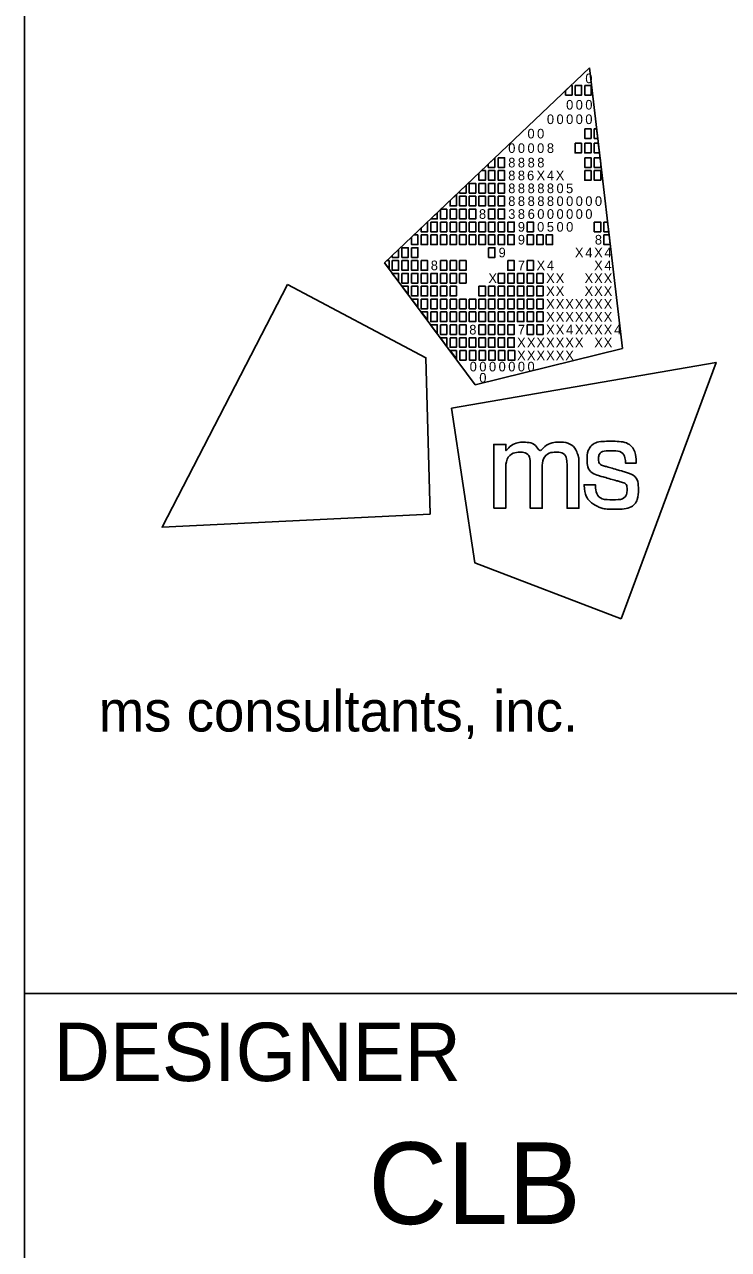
# Model space of a CAD drawing. Extents: x -0.2 to 34, y 0 to 22.
# Drawn here: x 32 to 33.207, y 2.061 to 4.16 of the extents above; entities that cross this region are included whole.
import ezdxf

# ---------------------------------------------------------------- set-up
doc = ezdxf.new("R2010")
doc.units = 0
doc.layers.add('SH_Border', color=7, linetype='Continuous')
doc.layers.add('SH_Data', color=7, linetype='Continuous')

msp = doc.modelspace()

# ---------------------------------------------------------------- linework, layer by layer
at = {"layer": 'SH_Border'}
for p, q in [((32, 0.5), (32, 21.5)), ((32.6175, 3.7519), (32.9688, 4.0861)), ((32.9688, 4.0861), (32.9688, 4.0861)), ((32.9688, 4.0861), (33.0253, 3.6052)), ((32.773, 3.543), (32.6175, 3.7519)), ((33.0253, 3.6052), (32.773, 3.543)), ((32, 2.5), (33.5, 2.5))]:
    msp.add_line(p, q, dxfattribs=at)
for points in [[(32.9279, 4.0472), (32.9369, 4.0558), (32.9389, 4.0558), (32.9389, 4.0393), (32.9279, 4.0393)], [(32.9444, 4.0558), (32.9554, 4.0558), (32.9554, 4.0393), (32.9444, 4.0393)], [(32.9609, 4.0558), (32.9719, 4.0558), (32.9719, 4.0393), (32.9609, 4.0393)], [(32.9606, 3.9815), (32.9716, 3.9815), (32.9716, 3.965), (32.9606, 3.965)], [(32.9771, 3.9815), (32.9811, 3.9815), (32.983, 3.965), (32.9771, 3.965)], [(32.9441, 3.9567), (32.9551, 3.9567), (32.9551, 3.9402), (32.9441, 3.9402)], [(32.9606, 3.9567), (32.9716, 3.9567), (32.9716, 3.9402), (32.9606, 3.9402)], [(32.9771, 3.9567), (32.984, 3.9567), (32.9859, 3.9402), (32.9771, 3.9402)], [(32.7953, 3.9211), (32.8064, 3.9316), (32.8064, 3.9154), (32.7953, 3.9154)], [(32.8123, 3.9319), (32.8233, 3.9319), (32.8233, 3.9154), (32.8123, 3.9154)], [(32.9606, 3.9319), (32.9716, 3.9319), (32.9716, 3.9154), (32.9606, 3.9154)], [(32.9771, 3.9319), (32.9869, 3.9319), (32.9881, 3.9218), (32.9881, 3.9154), (32.9771, 3.9154)], [(32.7958, 3.9099), (32.8068, 3.9099), (32.8068, 3.8934), (32.7958, 3.8934)], [(32.8123, 3.9099), (32.8233, 3.9099), (32.8233, 3.8934), (32.8123, 3.8934)], [(32.9606, 3.9099), (32.9716, 3.9099), (32.9716, 3.8934), (32.9606, 3.8934)], [(32.9771, 3.9099), (32.9881, 3.9099), (32.9881, 3.8934), (32.9771, 3.8934)], [(32.7627, 3.8879), (32.7737, 3.8879), (32.7737, 3.8714), (32.7627, 3.8714)], [(32.7793, 3.8879), (32.7903, 3.8879), (32.7903, 3.8714), (32.7793, 3.8714)], [(32.7958, 3.8879), (32.8068, 3.8879), (32.8068, 3.8714), (32.7958, 3.8714)], [(32.8123, 3.8879), (32.8233, 3.8879), (32.8233, 3.8714), (32.8123, 3.8714)], [(32.7462, 3.8659), (32.7572, 3.8659), (32.7572, 3.8494), (32.7462, 3.8494)], [(32.7627, 3.8659), (32.7737, 3.8659), (32.7737, 3.8494), (32.7627, 3.8494)], [(32.7793, 3.8659), (32.7903, 3.8659), (32.7903, 3.8494), (32.7793, 3.8494)], [(32.7958, 3.8659), (32.8068, 3.8659), (32.8068, 3.8494), (32.7958, 3.8494)], [(32.8123, 3.8659), (32.8233, 3.8659), (32.8233, 3.8494), (32.8123, 3.8494)], [(32.7297, 3.8439), (32.7407, 3.8439), (32.7407, 3.8273), (32.7297, 3.8273)], [(32.7462, 3.8439), (32.7572, 3.8439), (32.7572, 3.8273), (32.7462, 3.8273)], [(32.7627, 3.8439), (32.7737, 3.8439), (32.7737, 3.8273), (32.7627, 3.8273)], [(32.7958, 3.8439), (32.8068, 3.8439), (32.8068, 3.8273), (32.7958, 3.8273)], [(32.8123, 3.8439), (32.8233, 3.8439), (32.8233, 3.8273), (32.8123, 3.8273)], [(32.6967, 3.8218), (32.7077, 3.8218), (32.7077, 3.8053), (32.6967, 3.8053)], [(32.7132, 3.8218), (32.7242, 3.8218), (32.7242, 3.8053), (32.7132, 3.8053)], [(32.7297, 3.8218), (32.7407, 3.8218), (32.7407, 3.8053), (32.7297, 3.8053)], [(32.7462, 3.8218), (32.7572, 3.8218), (32.7572, 3.8053), (32.7462, 3.8053)], [(32.7627, 3.8218), (32.7737, 3.8218), (32.7737, 3.8053), (32.7627, 3.8053)], [(32.7793, 3.8218), (32.7903, 3.8218), (32.7903, 3.8053), (32.7793, 3.8053)], [(32.7958, 3.8218), (32.8068, 3.8218), (32.8068, 3.8053), (32.7958, 3.8053)], [(32.8123, 3.8218), (32.8233, 3.8218), (32.8233, 3.8053), (32.8123, 3.8053)], [(32.8288, 3.8218), (32.8398, 3.8218), (32.8398, 3.8053), (32.8288, 3.8053)], [(32.8618, 3.8218), (32.8728, 3.8218), (32.8728, 3.8053), (32.8618, 3.8053)], [(32.9771, 3.8218), (32.9881, 3.8218), (32.9881, 3.8053), (32.9771, 3.8053)], [(32.9935, 3.8218), (32.9998, 3.8218), (33.0018, 3.8053), (32.9935, 3.8053)], [(32.6802, 3.7998), (32.6912, 3.7998), (32.6912, 3.7833), (32.6802, 3.7833)], [(32.6967, 3.7998), (32.7077, 3.7998), (32.7077, 3.7833), (32.6967, 3.7833)], [(32.7132, 3.7998), (32.7242, 3.7998), (32.7242, 3.7833), (32.7132, 3.7833)], [(32.7297, 3.7998), (32.7407, 3.7998), (32.7407, 3.7833), (32.7297, 3.7833)], [(32.7462, 3.7998), (32.7572, 3.7998), (32.7572, 3.7833), (32.7462, 3.7833)], [(32.7627, 3.7998), (32.7737, 3.7998), (32.7737, 3.7833), (32.7627, 3.7833)], [(32.7793, 3.7998), (32.7903, 3.7998), (32.7903, 3.7833), (32.7793, 3.7833)], [(32.7958, 3.7998), (32.8068, 3.7998), (32.8068, 3.7833), (32.7958, 3.7833)], [(32.8123, 3.7998), (32.8233, 3.7998), (32.8233, 3.7833), (32.8123, 3.7833)], [(32.8288, 3.7998), (32.8398, 3.7998), (32.8398, 3.7833), (32.8288, 3.7833)], [(32.8618, 3.7998), (32.8728, 3.7998), (32.8728, 3.7833), (32.8618, 3.7833)], [(32.8783, 3.7998), (32.8893, 3.7998), (32.8893, 3.7833), (32.8783, 3.7833)], [(32.8947, 3.7998), (32.9057, 3.7998), (32.9057, 3.7833), (32.8947, 3.7833)], [(32.9935, 3.7998), (33.0024, 3.7998), (33.0044, 3.7833), (32.9935, 3.7833)], [(32.6471, 3.7778), (32.6581, 3.7778), (32.6581, 3.7613), (32.6471, 3.7613)], [(32.6637, 3.7778), (32.6747, 3.7778), (32.6747, 3.7613), (32.6637, 3.7613)], [(32.7958, 3.7778), (32.8068, 3.7778), (32.8068, 3.7613), (32.7958, 3.7613)], [(32.6306, 3.7558), (32.6416, 3.7558), (32.6416, 3.7393), (32.6306, 3.7393)], [(32.6471, 3.7558), (32.6581, 3.7558), (32.6581, 3.7393), (32.6471, 3.7393)], [(32.6637, 3.7558), (32.6747, 3.7558), (32.6747, 3.7393), (32.6637, 3.7393)], [(32.6802, 3.7558), (32.6912, 3.7558), (32.6912, 3.7393), (32.6802, 3.7393)], [(32.7132, 3.7558), (32.7242, 3.7558), (32.7242, 3.7393), (32.7132, 3.7393)], [(32.7297, 3.7558), (32.7407, 3.7558), (32.7407, 3.7393), (32.7297, 3.7393)], [(32.7462, 3.7558), (32.7572, 3.7558), (32.7572, 3.7393), (32.7462, 3.7393)], [(32.8288, 3.7558), (32.8398, 3.7558), (32.8398, 3.7393), (32.8288, 3.7393)], [(32.8618, 3.7558), (32.8728, 3.7558), (32.8728, 3.7393), (32.8618, 3.7393)], [(32.6306, 3.7338), (32.6416, 3.7338), (32.6416, 3.72)], [(32.6471, 3.7338), (32.6581, 3.7338), (32.6581, 3.7173), (32.6471, 3.7173)], [(32.6637, 3.7338), (32.6747, 3.7338), (32.6747, 3.7173), (32.6637, 3.7173)], [(32.6802, 3.7338), (32.6912, 3.7338), (32.6912, 3.7173), (32.6802, 3.7173)], [(32.6967, 3.7338), (32.7077, 3.7338), (32.7077, 3.7173), (32.6967, 3.7173)], [(32.7132, 3.7338), (32.7242, 3.7338), (32.7242, 3.7173), (32.7132, 3.7173)], [(32.7297, 3.7338), (32.7407, 3.7338), (32.7407, 3.7173), (32.7297, 3.7173)], [(32.7462, 3.7338), (32.7572, 3.7338), (32.7572, 3.7173), (32.7462, 3.7173)], [(32.8123, 3.7338), (32.8233, 3.7338), (32.8233, 3.7173), (32.8123, 3.7173)], [(32.8288, 3.7338), (32.8398, 3.7338), (32.8398, 3.7173), (32.8288, 3.7173)], [(32.8453, 3.7338), (32.8563, 3.7338), (32.8563, 3.7173), (32.8453, 3.7173)], [(32.8618, 3.7338), (32.8728, 3.7338), (32.8728, 3.7173), (32.8618, 3.7173)], [(32.8783, 3.7338), (32.8893, 3.7338), (32.8893, 3.7173), (32.8783, 3.7173)], [(32.6471, 3.7117), (32.6581, 3.7117), (32.6581, 3.698)], [(32.6637, 3.7117), (32.6747, 3.7117), (32.6747, 3.6952), (32.6637, 3.6952)], [(32.6802, 3.7117), (32.6912, 3.7117), (32.6912, 3.6952), (32.6802, 3.6952)], [(32.6967, 3.7117), (32.7077, 3.7117), (32.7077, 3.6952), (32.6967, 3.6952)], [(32.7132, 3.7117), (32.7242, 3.7117), (32.7242, 3.6952), (32.7132, 3.6952)], [(32.7297, 3.7117), (32.7407, 3.7117), (32.7407, 3.6952), (32.7297, 3.6952)], [(32.7793, 3.7117), (32.7903, 3.7117), (32.7903, 3.6952), (32.7793, 3.6952)], [(32.7958, 3.7117), (32.8068, 3.7117), (32.8068, 3.6952), (32.7958, 3.6952)], [(32.8123, 3.7117), (32.8233, 3.7117), (32.8233, 3.6952), (32.8123, 3.6952)], [(32.8288, 3.7117), (32.8398, 3.7117), (32.8398, 3.6952), (32.8288, 3.6952)], [(32.8453, 3.7117), (32.8563, 3.7117), (32.8563, 3.6952), (32.8453, 3.6952)], [(32.8618, 3.7117), (32.8728, 3.7117), (32.8728, 3.6952), (32.8618, 3.6952)], [(32.8783, 3.7117), (32.8893, 3.7117), (32.8893, 3.6952), (32.8783, 3.6952)], [(32.6637, 3.6897), (32.6747, 3.6897), (32.6747, 3.676)], [(32.6747, 3.6897), (32.6747, 3.6897), (32.6747, 3.6897)], [(32.6802, 3.6897), (32.6912, 3.6897), (32.6912, 3.6732), (32.6802, 3.6732)], [(32.6967, 3.6897), (32.7077, 3.6897), (32.7077, 3.6732), (32.6967, 3.6732)], [(32.7132, 3.6897), (32.7242, 3.6897), (32.7242, 3.6732), (32.7132, 3.6732)], [(32.7297, 3.6897), (32.7407, 3.6897), (32.7407, 3.6732), (32.7297, 3.6732)], [(32.7462, 3.6897), (32.7572, 3.6897), (32.7572, 3.6732), (32.7462, 3.6732)], [(32.7627, 3.6897), (32.7737, 3.6897), (32.7737, 3.6732), (32.7627, 3.6732)], [(32.7793, 3.6897), (32.7903, 3.6897), (32.7903, 3.6732), (32.7793, 3.6732)], [(32.7958, 3.6897), (32.8068, 3.6897), (32.8068, 3.6732), (32.7958, 3.6732)], [(32.8123, 3.6897), (32.8233, 3.6897), (32.8233, 3.6732), (32.8123, 3.6732)], [(32.8288, 3.6897), (32.8398, 3.6897), (32.8398, 3.6732), (32.8288, 3.6732)], [(32.8453, 3.6897), (32.8563, 3.6897), (32.8563, 3.6732), (32.8453, 3.6732)], [(32.8618, 3.6897), (32.8728, 3.6897), (32.8728, 3.6732), (32.8618, 3.6732)], [(32.8783, 3.6897), (32.8893, 3.6897), (32.8893, 3.6732), (32.8783, 3.6732)], [(32.6802, 3.6677), (32.6912, 3.6677), (32.6912, 3.654)], [(32.6967, 3.6677), (32.7077, 3.6677), (32.7077, 3.6512), (32.6967, 3.6512)], [(32.7132, 3.6677), (32.7242, 3.6677), (32.7242, 3.6512), (32.7132, 3.6512)], [(32.7297, 3.6677), (32.7407, 3.6677), (32.7407, 3.6512), (32.7297, 3.6512)], [(32.7462, 3.6677), (32.7572, 3.6677), (32.7572, 3.6512), (32.7462, 3.6512)], [(32.7627, 3.6677), (32.7737, 3.6677), (32.7737, 3.6512), (32.7627, 3.6512)], [(32.7793, 3.6677), (32.7903, 3.6677), (32.7903, 3.6512), (32.7793, 3.6512)], [(32.7958, 3.6677), (32.8068, 3.6677), (32.8068, 3.6512), (32.7958, 3.6512)], [(32.8123, 3.6677), (32.8233, 3.6677), (32.8233, 3.6512), (32.8123, 3.6512)], [(32.8288, 3.6677), (32.8398, 3.6677), (32.8398, 3.6512), (32.8288, 3.6512)], [(32.8453, 3.6677), (32.8563, 3.6677), (32.8563, 3.6512), (32.8453, 3.6512)], [(32.8618, 3.6677), (32.8728, 3.6677), (32.8728, 3.6512), (32.8618, 3.6512)], [(32.8783, 3.6677), (32.8893, 3.6677), (32.8893, 3.6512), (32.8783, 3.6512)], [(32.7077, 3.6305), (32.6965, 3.6457), (32.7077, 3.6457)], [(32.7132, 3.6457), (32.7242, 3.6457), (32.7242, 3.6292), (32.7132, 3.6292)], [(32.7297, 3.6457), (32.7407, 3.6457), (32.7407, 3.6292), (32.7297, 3.6292)], [(32.7462, 3.6457), (32.7572, 3.6457), (32.7572, 3.6292), (32.7462, 3.6292)], [(32.7793, 3.6457), (32.7903, 3.6457), (32.7903, 3.6292), (32.7793, 3.6292)], [(32.7958, 3.6457), (32.8068, 3.6457), (32.8068, 3.6292), (32.7958, 3.6292)], [(32.8123, 3.6457), (32.8233, 3.6457), (32.8233, 3.6292), (32.8123, 3.6292)], [(32.8288, 3.6457), (32.8398, 3.6457), (32.8398, 3.6292), (32.8288, 3.6292)], [(32.8618, 3.6457), (32.8728, 3.6457), (32.8728, 3.6292), (32.8618, 3.6292)], [(32.8783, 3.6457), (32.8893, 3.6457), (32.8893, 3.6292), (32.8783, 3.6292)], [(32.724, 3.6082), (32.7132, 3.6237), (32.7242, 3.6237)], [(32.7297, 3.6237), (32.7407, 3.6237), (32.7407, 3.6072), (32.7297, 3.6072)], [(32.7462, 3.6237), (32.7572, 3.6237), (32.7572, 3.6072), (32.7462, 3.6072)], [(32.7627, 3.6237), (32.7737, 3.6237), (32.7737, 3.6072), (32.7627, 3.6072)], [(32.7793, 3.6237), (32.7903, 3.6237), (32.7903, 3.6072), (32.7793, 3.6072)], [(32.7958, 3.6237), (32.8068, 3.6237), (32.8068, 3.6072), (32.7958, 3.6072)], [(32.8123, 3.6237), (32.8233, 3.6237), (32.8233, 3.6072), (32.8123, 3.6072)], [(32.8288, 3.6237), (32.8398, 3.6237), (32.8398, 3.6072), (32.8288, 3.6072)], [(32.7302, 3.6017), (32.7407, 3.6017), (32.7408, 3.5875)], [(32.7463, 3.6017), (32.7573, 3.6017), (32.7573, 3.5852), (32.7463, 3.5852)], [(32.763, 3.6017), (32.774, 3.6017), (32.774, 3.5852), (32.763, 3.5852)], [(32.7794, 3.6017), (32.7904, 3.6017), (32.7904, 3.5852), (32.7794, 3.5852)], [(32.796, 3.6017), (32.807, 3.6017), (32.807, 3.5852), (32.796, 3.5852)], [(32.8129, 3.6017), (32.8239, 3.6017), (32.8239, 3.5851), (32.8129, 3.5851)], [(32.8296, 3.6017), (32.8406, 3.6017), (32.8406, 3.5851), (32.8296, 3.5851)]]:
    msp.add_lwpolyline(points, close=True, dxfattribs=at)
for points in [[(32.7903, 3.9099), (32.7836, 3.9099), (32.7793, 3.9058), (32.7793, 3.8934), (32.7903, 3.8934), (32.7903, 3.9099)], [(32.7572, 3.8849), (32.7462, 3.8744), (32.7462, 3.8714), (32.7572, 3.8714), (32.7572, 3.8849)], [(32.7407, 3.8691), (32.7297, 3.8587), (32.7297, 3.8494), (32.7407, 3.8494), (32.7407, 3.8691)], [(32.7242, 3.8439), (32.7141, 3.8439), (32.7132, 3.843), (32.7132, 3.8273), (32.7242, 3.8273), (32.7242, 3.8439)], [(32.6912, 3.822), (32.6802, 3.8115), (32.6802, 3.8053), (32.6912, 3.8053), (32.6912, 3.822)], [(32.7077, 3.8377), (32.6968, 3.8273), (32.7077, 3.8273), (32.7077, 3.8377)], [(32.6747, 3.7998), (32.6679, 3.7998), (32.6637, 3.7958), (32.6637, 3.7833), (32.6747, 3.7833), (32.6747, 3.7998)], [(32.6416, 3.7749), (32.6306, 3.7644), (32.6306, 3.7613), (32.6416, 3.7613), (32.6416, 3.7749)], [(32.6251, 3.7558), (32.6216, 3.7558), (32.6175, 3.7519), (32.6251, 3.7417), (32.6251, 3.7558)], [(32.4512, 3.7149), (32.2359, 3.2988), (32.6956, 3.3215), (32.6884, 3.5892), (32.4512, 3.7149)], [(33.0229, 3.1422), (33.1859, 3.5814), (32.7324, 3.5029), (32.7722, 3.2381), (33.0229, 3.1422)]]:
    msp.add_lwpolyline(points, dxfattribs=at)
for points in [[(32.8048, 3.3315), (32.8048, 3.3315), (32.8048, 3.4409), (32.8048, 3.4409), (32.8048, 3.4409), (32.8255, 3.4409), (32.8255, 3.4409), (32.8255, 3.4409), (32.8255, 3.4297), (32.8255, 3.4297), (32.8346, 3.4399), (32.8457, 3.4445), (32.8555, 3.4445), (32.8688, 3.4445), (32.8791, 3.4372), (32.8837, 3.4266), (32.8915, 3.4381), (32.905, 3.4446), (32.9166, 3.4446), (32.9325, 3.4446), (32.9451, 3.435), (32.9494, 3.4213), (32.9494, 3.4212), (32.9494, 3.4212), (32.9494, 3.4212), (32.9501, 3.419), (32.9506, 3.4172), (32.9506, 3.4071), (32.9506, 3.4071), (32.9506, 3.3314), (32.9506, 3.3314), (32.9506, 3.3314), (32.9303, 3.3314), (32.9303, 3.3314), (32.9303, 3.3314), (32.9303, 3.4048), (32.9303, 3.4048), (32.9303, 3.4201), (32.9219, 3.4274), (32.911, 3.4274), (32.8995, 3.4274), (32.8879, 3.4171), (32.8879, 3.4001), (32.8879, 3.4001), (32.8879, 3.3315), (32.8879, 3.3315), (32.8879, 3.3315), (32.8674, 3.3315), (32.8674, 3.3315), (32.8674, 3.3315), (32.8674, 3.4059), (32.8674, 3.4059), (32.8674, 3.4203), (32.8588, 3.4274), (32.8496, 3.4274), (32.8384, 3.4274), (32.8254, 3.417), (32.8254, 3.3962), (32.8254, 3.3962), (32.8254, 3.3315), (32.8254, 3.3315), (32.8254, 3.3315), (32.8048, 3.3315), (32.8048, 3.3315)], [(32.9595, 3.3709), (32.9595, 3.3709), (32.9595, 3.3717), (32.9595, 3.3717), (32.9595, 3.3717), (32.9603, 3.3717), (32.9603, 3.3717), (32.9603, 3.3717), (32.9783, 3.3717), (32.9783, 3.3717), (32.9783, 3.3717), (32.9789, 3.3717), (32.9789, 3.3717), (32.9789, 3.3717), (32.979, 3.371), (32.979, 3.371), (32.9803, 3.3554), (32.9887, 3.346), (33.009, 3.346), (33.0273, 3.346), (33.0333, 3.3554), (33.0333, 3.3631), (33.0333, 3.3732), (33.0256, 3.3758), (33.0175, 3.378), (33.0175, 3.378), (32.987, 3.3867), (32.987, 3.3867), (32.972, 3.3909), (32.9648, 3.4019), (32.9648, 3.4142), (32.9648, 3.4303), (32.9768, 3.4462), (33.0052, 3.4462), (33.0348, 3.4462), (33.0489, 3.4285), (33.0489, 3.4095), (33.0489, 3.4095), (33.0489, 3.4087), (33.0489, 3.4087), (33.0489, 3.4087), (33.0482, 3.4087), (33.0482, 3.4087), (33.0482, 3.4087), (33.0312, 3.4087), (33.0312, 3.4087), (33.0312, 3.4087), (33.0305, 3.4087), (33.0305, 3.4087), (33.0305, 3.4087), (33.0305, 3.4094), (33.0305, 3.4094), (33.0301, 3.4208), (33.0226, 3.43), (33.0056, 3.43), (32.9891, 3.43), (32.9843, 3.4218), (32.9843, 3.4157), (32.9843, 3.4108), (32.9869, 3.4059), (32.9959, 3.4033), (32.9959, 3.4033), (33.0255, 3.3948), (33.0255, 3.3948), (33.0462, 3.3889), (33.0527, 3.3777), (33.0527, 3.3639), (33.0527, 3.3462), (33.041, 3.3298), (33.0087, 3.3298), (32.9952, 3.3298), (32.9877, 3.3321), (32.9823, 3.3348), (32.969, 3.3414), (32.9609, 3.3536), (32.9595, 3.3709)]]:
    msp.add_open_spline(points, degree=3, dxfattribs=at)
at = {"layer": 'SH_Data'}
msp.add_line((32.75, 3.5), (32.75, 3.5), dxfattribs=at)

# ---------------------------------------------------------------- texts
at = {"layer": 'SH_Border'}
for s, height, p in [('0', 0.0165, (32.9617, 4.0597)), ('0', 0.0165, (32.9288, 4.0145)), ('0', 0.0165, (32.9452, 4.0145)), ('0', 0.0165, (32.9617, 4.0145)), ('0', 0.0165, (32.8958, 3.9897)), ('0', 0.0165, (32.9123, 3.9897)), ('0', 0.0165, (32.9288, 3.9897)), ('0', 0.0165, (32.9452, 3.9897)), ('0', 0.0165, (32.9617, 3.9897)), ('0', 0.0165, (32.8625, 3.965)), ('0', 0.0165, (32.879, 3.965)), ('0', 0.0165, (32.8295, 3.9402)), ('0', 0.0165, (32.846, 3.9402)), ('0', 0.0165, (32.8625, 3.9402)), ('0', 0.0165, (32.879, 3.9402)), ('8', 0.0165, (32.8958, 3.9402)), ('8', 0.0165, (32.8295, 3.9154)), ('8', 0.0165, (32.846, 3.9154)), ('8', 0.0165, (32.8628, 3.9154)), ('8', 0.0165, (32.8793, 3.9154)), ('8', 0.0165, (32.8295, 3.8934)), ('8', 0.0165, (32.846, 3.8934)), ('6', 0.0165, (32.8618, 3.8934)), ('X', 0.0165, (32.8781, 3.8934)), ('4', 0.0165, (32.8958, 3.8934)), ('X', 0.0165, (32.911, 3.8934)), ('8', 0.0165, (32.8295, 3.8713)), ('8', 0.0165, (32.846, 3.8713)), ('8', 0.0165, (32.8628, 3.8713)), ('8', 0.0165, (32.8794, 3.8713)), ('8', 0.0165, (32.8958, 3.8713)), ('0', 0.0165, (32.9123, 3.8713)), ('5', 0.0165, (32.9287, 3.8713)), ('8', 0.0165, (32.8295, 3.8494)), ('8', 0.0165, (32.846, 3.8494)), ('8', 0.0165, (32.8628, 3.8494)), ('8', 0.0165, (32.8794, 3.8494)), ('8', 0.0165, (32.8958, 3.8494)), ('0', 0.0165, (32.9123, 3.8494)), ('0', 0.0165, (32.9288, 3.8494)), ('0', 0.0165, (32.9452, 3.8494)), ('0', 0.0165, (32.9617, 3.8494)), ('0', 0.0165, (32.9782, 3.8494)), ('8', 0.0165, (32.7793, 3.8273)), ('3', 0.0165, (32.8295, 3.8273)), ('8', 0.0165, (32.846, 3.8273)), ('6', 0.0165, (32.8629, 3.8273)), ('0', 0.0165, (32.8793, 3.8273)), ('0', 0.0165, (32.8958, 3.8273)), ('0', 0.0165, (32.9123, 3.8273)), ('0', 0.0165, (32.9288, 3.8273)), ('0', 0.0165, (32.9452, 3.8273)), ('0', 0.0165, (32.9617, 3.8273)), ('9', 0.0165, (32.846, 3.8053)), ('0', 0.0165, (32.879, 3.8053)), ('5', 0.0165, (32.8957, 3.8053)), ('0', 0.0165, (32.9123, 3.8053)), ('0', 0.0165, (32.9288, 3.8053)), ('9', 0.0165, (32.846, 3.7833)), ('8', 0.0165, (32.9781, 3.7833)), ('9', 0.0165, (32.813, 3.7613)), ('X', 0.0165, (32.9439, 3.7613)), ('4', 0.0165, (32.9617, 3.7613)), ('X', 0.0165, (32.9769, 3.7613)), ('4', 0.0165, (32.9946, 3.7613)), ('8', 0.0165, (32.6967, 3.7393)), ('7', 0.0165, (32.846, 3.7393)), ('X', 0.0165, (32.8781, 3.7393)), ('4', 0.0165, (32.8958, 3.7393)), ('X', 0.0165, (32.9769, 3.7393)), ('4', 0.0165, (32.9946, 3.7393)), ('X', 0.0165, (32.7955, 3.7173)), ('X', 0.0165, (32.8945, 3.7173)), ('X', 0.0165, (32.911, 3.7173)), ('X', 0.0165, (32.9604, 3.7173)), ('X', 0.0165, (32.9769, 3.7173)), ('X', 0.0165, (32.9933, 3.7173)), ('X', 0.0165, (32.8945, 3.6952)), ('X', 0.0165, (32.911, 3.6952)), ('X', 0.0165, (32.9604, 3.6952)), ('X', 0.0165, (32.9769, 3.6952)), ('X', 0.0165, (32.9933, 3.6952)), ('X', 0.0165, (32.8945, 3.6732)), ('X', 0.0165, (32.911, 3.6732)), ('X', 0.0165, (32.9274, 3.6732)), ('X', 0.0165, (32.9439, 3.6732)), ('X', 0.0165, (32.9604, 3.6732)), ('X', 0.0165, (32.9769, 3.6732)), ('X', 0.0165, (32.9933, 3.6732)), ('X', 0.0165, (32.8945, 3.6512)), ('X', 0.0165, (32.911, 3.6512)), ('X', 0.0165, (32.9274, 3.6512)), ('X', 0.0165, (32.9439, 3.6512)), ('X', 0.0165, (32.9604, 3.6512)), ('X', 0.0165, (32.9769, 3.6512)), ('X', 0.0165, (32.9933, 3.6512)), ('8', 0.0165, (32.7627, 3.6292)), ('7', 0.0165, (32.846, 3.6292)), ('X', 0.0165, (32.8945, 3.6292)), ('X', 0.0165, (32.911, 3.6292)), ('4', 0.0165, (32.9288, 3.6292)), ('X', 0.0165, (32.9439, 3.6292)), ('X', 0.0165, (32.9604, 3.6292)), ('X', 0.0165, (32.9769, 3.6292)), ('X', 0.0165, (32.9933, 3.6292)), ('4', 0.0165, (33.0111, 3.6292)), ('X', 0.0165, (32.8447, 3.6072)), ('X', 0.0165, (32.8616, 3.6072)), ('X', 0.0165, (32.878, 3.6072)), ('X', 0.0165, (32.8945, 3.6072)), ('X', 0.0165, (32.911, 3.6072)), ('X', 0.0165, (32.9274, 3.6072)), ('X', 0.0165, (32.9439, 3.6072)), ('X', 0.0165, (32.9771, 3.6072)), ('X', 0.0165, (32.9933, 3.6072)), ('X', 0.0165, (32.8447, 3.5851)), ('X', 0.0165, (32.8616, 3.5851)), ('X', 0.0165, (32.878, 3.5851)), ('X', 0.0165, (32.8945, 3.5851)), ('X', 0.0165, (32.911, 3.5851)), ('X', 0.0165, (32.9274, 3.5851)), ('0', 0.0165, (32.7634, 3.5659)), ('0', 0.0165, (32.7799, 3.5659)), ('0', 0.0165, (32.7965, 3.5659)), ('0', 0.0165, (32.813, 3.5659)), ('0', 0.0165, (32.8295, 3.5659)), ('0', 0.0165, (32.846, 3.5659)), ('0', 0.0165, (32.8625, 3.5659)), ('0', 0.0165, (32.7799, 3.5467)), ('ms consultants, inc.', 0.07, (32.1273, 2.9489))]:
    msp.add_text(s, height=height, rotation=360, dxfattribs=at).set_placement(p)
at = {"layer": 'SH_Data'}
for s, height, p in [('DESIGNER', 0.1, (32.05, 2.35)), ('CLB', 0.14, (32.5896, 2.105))]:
    msp.add_text(s, height=height, dxfattribs=at).set_placement(p)

doc.saveas('drawing.dxf')
